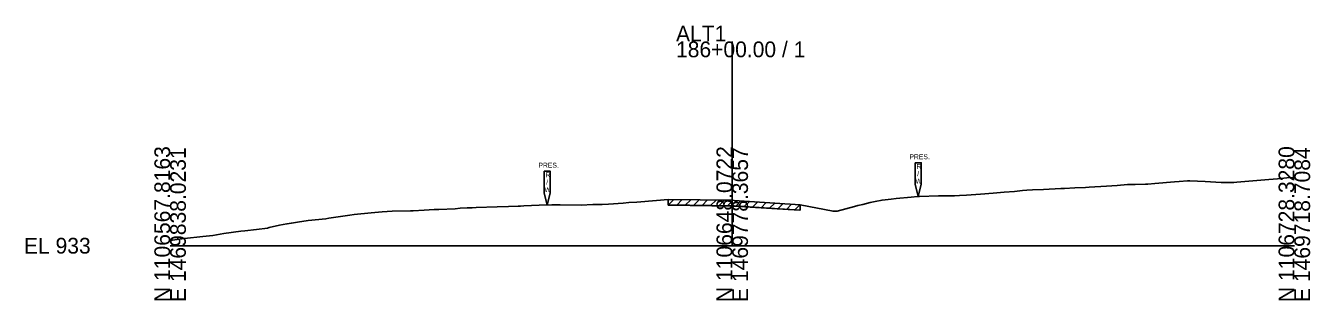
# Model space of a CAD drawing. Extents: x -26 to 2203, y -10 to 19568.
# Drawn here: x 1974.3 to 2202.8, y 7990.3 to 8039.1 of the extents above; entities that cross this region are included whole.
import ezdxf

# ---------------------------------------------------------------- set-up
doc = ezdxf.new("R2010")
doc.units = 0
for name, color, linetype in [('RD_GPK_XS_Cell', 7, 'Continuous'), ('RD_XS_ExGround', 7, 'Continuous'), ('RD_XS_ExPaveRet', 7, 'Continuous'), ('RD_XS_ExRW', 7, 'Continuous')]:
    doc.layers.add(name, color=color, linetype=linetype)

msp = doc.modelspace()

# ---------------------------------------------------------------- linework, layer by layer
at = {"layer": 'RD_GPK_XS_Cell'}
for p, q in [((2100, 8000), (2100, 8036.29)), ((2000, 8000), (2100, 8000)), ((2100, 8000), (2200, 8000))]:
    msp.add_line(p, q, dxfattribs=at)
at = {"layer": 'RD_XS_ExGround'}
msp.add_lwpolyline([(2000, 8000.94), (2002.1, 8001.21), (2002.55, 8001.27), (2005.84, 8001.61), (2007.58, 8001.84), (2009.57, 8002.18), (2012.61, 8002.6), (2013.31, 8002.66), (2015.34, 8002.91), (2017.3, 8003.14), (2017.64, 8003.22), (2019.45, 8003.64), (2020.79, 8003.87), (2021.59, 8004.01), (2022.67, 8004.17), (2024.53, 8004.46), (2027.7, 8004.79), (2028.26, 8004.87), (2029.91, 8005.12), (2032, 8005.45), (2032.73, 8005.53), (2035.74, 8005.84), (2037.75, 8006.04), (2039.48, 8006.12), (2042.78, 8006.2), (2043.22, 8006.22), (2045.18, 8006.29), (2046.95, 8006.41), (2047.32, 8006.42), (2047.81, 8006.43), (2050.69, 8006.58), (2051.61, 8006.65), (2052.84, 8006.72), (2053.75, 8006.76), (2054.43, 8006.8), (2058.17, 8006.91), (2060.19, 8006.98), (2061.91, 8007.03), (2062.33, 8007.03), (2062.9, 8007.08), (2065.64, 8007.22), (2067.93, 8007.24), (2069.38, 8007.26), (2073.12, 8007.22), (2075.19, 8007.32), (2076.86, 8007.32), (2077.98, 8007.38), (2080.6, 8007.58), (2081.63, 8007.66), (2083.01, 8007.74), (2083.77, 8007.79), (2088.63, 8008.24), (2100, 8008.07), (2100.34, 8008.06), (2112.08, 8007.29), (2117.93, 8006.14), (2118.33, 8006.14), (2118.67, 8006.14), (2121.76, 8006.96), (2122.37, 8007.14), (2123.24, 8007.35), (2124.51, 8007.68), (2125.45, 8007.86), (2126.65, 8008.1), (2128.27, 8008.29), (2129.19, 8008.38), (2131.86, 8008.63), (2132.93, 8008.72), (2133.3, 8008.75), (2136.67, 8008.86), (2137.38, 8008.87), (2138.33, 8008.87), (2139.52, 8008.89), (2140.41, 8008.93), (2141.66, 8009.01), (2143.36, 8009.11), (2144.14, 8009.16), (2146.42, 8009.34), (2148.39, 8009.49), (2150.24, 8009.64), (2151.62, 8009.8), (2152.39, 8009.89), (2153.41, 8009.92), (2155.36, 8010), (2158.44, 8010.17), (2159.1, 8010.19), (2160.96, 8010.31), (2162.83, 8010.36), (2163.47, 8010.38), (2166.57, 8010.56), (2168.5, 8010.72), (2170.31, 8010.86), (2171.68, 8010.9), (2173.53, 8010.94), (2173.93, 8010.95), (2175.2, 8011.05), (2178.7, 8011.34), (2179.51, 8011.39), (2180.98, 8011.53), (2181.41, 8011.52), (2184.12, 8011.39), (2187.01, 8011.26), (2187.62, 8011.24), (2189.26, 8011.26), (2189.77, 8011.27), (2195.44, 8011.75), (2196.99, 8011.87), (2198.67, 8012.04), (2200, 8012.1)], dxfattribs=at)
at = {"layer": 'RD_XS_ExPaveRet'}
for p, q in [((2088.63, 8008.24), (2088.63, 8007.24)), ((2088.63, 8007.23), (2088.63, 8008.23)), ((2088.63, 8007.23), (2089.62, 8008.22)), ((2090.13, 8007.21), (2091.12, 8008.2)), ((2091.63, 8007.19), (2092.62, 8008.17)), ((2093.13, 8007.16), (2094.12, 8008.15)), ((2094.63, 8007.14), (2095.62, 8008.13)), ((2096.13, 8007.12), (2097.12, 8008.1)), ((2097.63, 8007.09), (2098.62, 8008.08)), ((2099.13, 8007.07), (2100.12, 8008.06)), ((2100.63, 8007.05), (2101.55, 8007.97)), ((2102.13, 8006.96), (2103.05, 8007.87)), ((2088.63, 8007.24), (2100, 8007.07)), ((2088.63, 8007.23), (2100.27, 8007.05)), ((2100, 8007.07), (2100.34, 8007.06)), ((2100.27, 8007.05), (2109.96, 8006.42)), ((2100.28, 8007.08), (2112.01, 8006.31)), ((2103.63, 8006.86), (2104.55, 8007.77)), ((2105.13, 8006.76), (2106.05, 8007.68)), ((2106.63, 8006.66), (2107.55, 8007.58)), ((2108.13, 8006.56), (2109.05, 8007.48)), ((2109.63, 8006.46), (2110.55, 8007.38)), ((2109.96, 8006.42), (2112.01, 8006.29)), ((2111.13, 8006.37), (2112.04, 8007.28)), ((2112.01, 8006.31), (2112.08, 8006.3)), ((2112.01, 8006.29), (2112.08, 8006.27)), ((2112.08, 8007.3), (2112.08, 8006.3)), ((2112.08, 8007.29), (2112.08, 8006.29))]:
    msp.add_line(p, q, dxfattribs=at)
at = {"layer": 'RD_XS_ExRW'}
for points in [[(2132.52, 8014.75), (2133.62, 8014.75), (2133.62, 8010.92), (2133.07, 8008.73), (2132.52, 8010.92)], [(2066.52, 8013.24), (2067.62, 8013.24), (2067.62, 8009.41), (2067.07, 8007.23), (2066.52, 8009.41)]]:
    msp.add_lwpolyline(points, close=True, dxfattribs=at)

# ---------------------------------------------------------------- texts
at = {"layer": 'RD_GPK_XS_Cell'}
for s, p in [('ALT1', (2090, 8036.29)), ('186+00.00 / 1', (2090, 8033.49)), ('EL 933', (1974, 7998.6))]:
    msp.add_text(s, height=2.8, dxfattribs=at).set_placement(p)
for s, p in [('N 1106567.8163', (2000, 7990)), ('E 1469838.0231', (2002.8, 7990)), ('N 1106648.0722', (2100, 7990)), ('E 1469778.3657', (2102.8, 7990)), ('N 1106728.3280', (2200, 7990)), ('E 1469718.7084', (2202.8, 7990))]:
    msp.add_text(s, height=2.8, rotation=90, dxfattribs=at).set_placement(p)
at = {"layer": 'RD_XS_ExRW'}
for s, p in [('PRES.', (2065.52, 8013.87)), ('PRES.', (2131.52, 8015.37)), ('R', (2066.78, 8012.15)), ('R', (2132.78, 8013.65)), ('/', (2132.9, 8012.34)), ('W', (2066.6, 8009.52)), ('/', (2066.9, 8010.84)), ('W', (2132.6, 8011.03))]:
    msp.add_text(s, height=0.875, dxfattribs=at).set_placement(p)

doc.saveas('drawing.dxf')
